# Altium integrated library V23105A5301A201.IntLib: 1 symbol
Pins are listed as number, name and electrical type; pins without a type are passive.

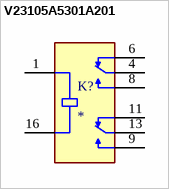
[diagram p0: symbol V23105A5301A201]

## V23105A5301A201
designator K?
Industrial Control, Relays, I/O Modules, spdt, relay, Relays and Accessories; MF: TE Connectivity; MP: V23105-A5301-A201
footprint RELAY_9-1393792-3
pins: 1 COIL1, 4 COM1, 6 NC1, 8 NO1, 9 NO2, 11 NC2, 13 COM2, 16 COIL2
